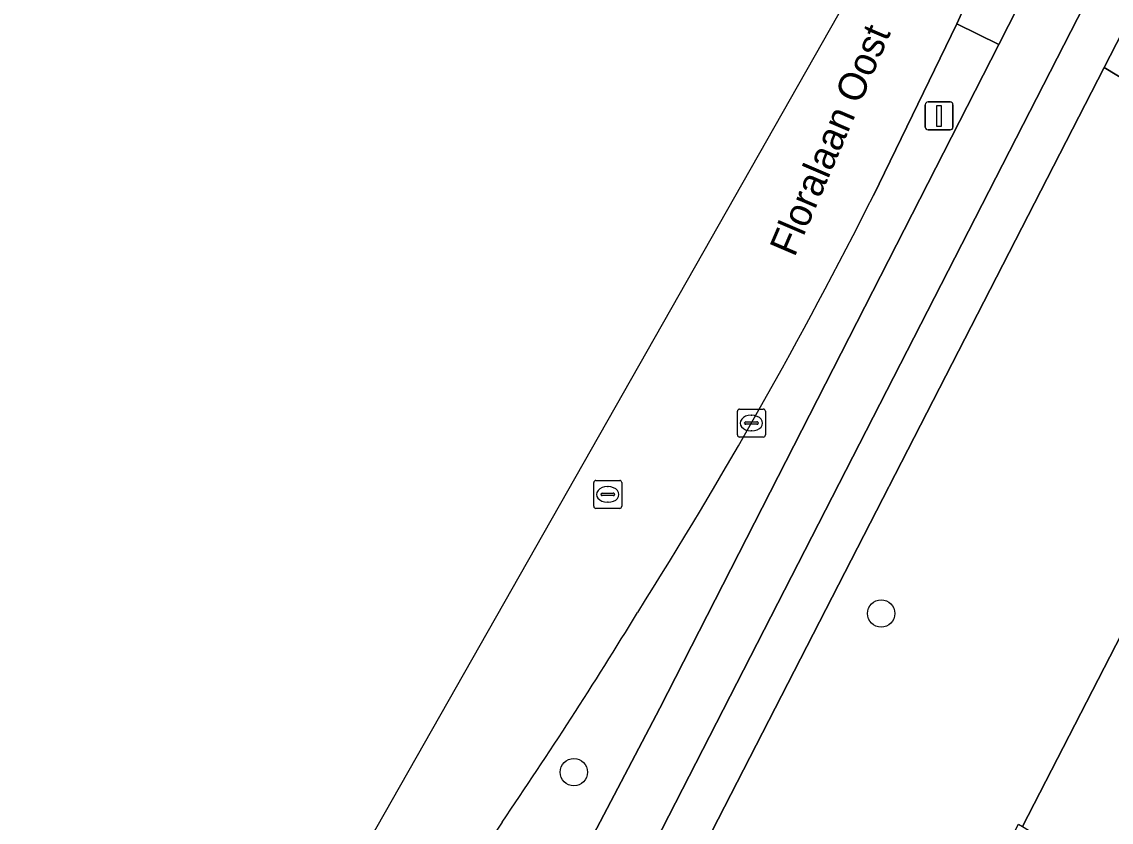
# Model space of a CAD drawing. Extents: x 162661 to 163484, y 380247 to 381230.
# Drawn here: x 163062.37 to 163101.35, y 380942.48 to 380971.11 of the extents above; entities that cross this region are included whole.
import ezdxf

# ---------------------------------------------------------------- set-up
doc = ezdxf.new("R2010")
doc.units = 0
for name, color, linetype in [('IMGEO_Berm_groen', 7, 'Continuous'), ('IMGEO_Berm_open', 7, 'Continuous'), ('IMGEO_Boom', 7, 'Continuous'), ('IMGEO_Erf', 7, 'Continuous'), ('IMGEO_Fietspad_open', 7, 'Continuous'), ('IMGEO_Gemengd_bos', 7, 'Continuous'), ('IMGEO_Kolk', 7, 'Continuous'), ('IMGEO_Lichtmast', 7, 'Continuous'), ('IMGEO_Openbare_ruimte_label', 7, 'Continuous'), ('IMGEO_Rijbaan_lokaal_gesloten', 7, 'Continuous'), ('IMGEO_Rioolput', 7, 'Continuous'), ('IMGEO_Voetpad_open', 7, 'Continuous')]:
    doc.layers.add(name, color=color, linetype=linetype)

msp = doc.modelspace()

# ---------------------------------------------------------------- linework, layer by layer
at = {"layer": 'IMGEO_Berm_groen'}
msp.add_lwpolyline([(163099.718, 380979.621), (163095.831, 380971.041), (163097.334, 380970.302), (163108.722, 380992.689), (163112.397, 380999.985), (163113.278, 381001.751)], dxfattribs=at)
at = {"layer": 'IMGEO_Berm_open'}
for points in [[(163097.334, 380970.302), (163095.831, 380971.041), (163092.842, 380964.895)], [(163079.556, 380942.482), (163078.602, 380941.045), (163081.312, 380939.161), (163085.202, 380946.557), (163097.334, 380970.302)]]:
    msp.add_lwpolyline(points, dxfattribs=at)
for centre, radius, start, end in [((162936.719, 381043.38), 174.741, 327.69234, 333.31081), ((162932.371, 381042.958), 178.21, 325.68046, 328.55401)]:
    msp.add_arc(centre, radius, start, end, dxfattribs=at)
at = {"layer": 'IMGEO_Boom'}
for centre in [(163093.122, 380949.947), (163082.127, 380944.274)]:
    msp.add_circle(centre, 0.489, dxfattribs=at)
at = {"layer": 'IMGEO_Erf'}
msp.add_lwpolyline([(163104.225, 380954.07), (163098.182, 380942.327), (163101.335, 380940.389), (163100.148, 380938.457), (163097.141, 380940.305), (163093.264, 380932.77), (163097.903, 380930.325), (163099.345, 380933.063), (163100.909, 380932.238), (163102.526, 380931.386), (163101.081, 380928.646), (163105.57, 380926.281)], dxfattribs=at)
at = {"layer": 'IMGEO_Fietspad_open'}
for points in [[(163113.278, 381001.751), (163112.397, 380999.985), (163108.722, 380992.689), (163097.334, 380970.302), (163085.202, 380946.557), (163081.312, 380939.161), (163078.602, 380941.045)], [(163078.572, 380932.781), (163078.201, 380932.005), (163077.707, 380931.721), (163077.359, 380931.919), (163078.839, 380929.669), (163080.32, 380932.543), (163082.573, 380934.938), (163082.967, 380936.912), (163083.252, 380937.877), (163083.627, 380938.938), (163084.062, 380939.851), (163114.537, 380999.295)]]:
    msp.add_lwpolyline(points, dxfattribs=at)
at = {"layer": 'IMGEO_Gemengd_bos'}
msp.add_lwpolyline([(163101.756, 380970.755), (163101.103, 380969.474), (163106.127, 380966.443), (163109.929, 380965.978), (163111.192, 380968.563), (163116.243, 380977.443), (163125.384, 380995.798), (163127.445, 380995.227), (163128.473, 381000), (163129.592, 381005.204), (163119.2, 381007.44), (163118.862, 381006.215), (163118.19, 381004.006), (163116.667, 381000)], close=True, dxfattribs=at)
for points in [[(163104.225, 380954.07), (163108.592, 380963.242), (163109.929, 380965.978), (163106.127, 380966.443), (163101.103, 380969.474), (163085.699, 380939.507), (163085.075, 380938.231)], [(163088.006, 380923.155), (163088.066, 380923.12), (163088.126, 380923.086), (163089.051, 380924.835), (163091.396, 380929.252), (163093.264, 380932.77), (163097.141, 380940.305), (163096.996, 380940.394), (163098.036, 380942.417), (163098.182, 380942.327), (163104.225, 380954.07)]]:
    msp.add_lwpolyline(points, dxfattribs=at)
at = {"layer": 'IMGEO_Kolk'}
for p, q in [((163088.053, 380957.259), (163088.905, 380957.259)), ((163087.978, 380956.333), (163087.978, 380957.185)), ((163088.466, 380957.039), (163088.491, 380957.039)), ((163088.979, 380957.185), (163088.979, 380956.333)), ((163088.237, 380956.753), (163088.237, 380956.765)), ((163088.675, 380956.716), (163088.277, 380956.716)), ((163088.28, 380956.802), (163088.678, 380956.802)), ((163088.489, 380956.479), (163088.464, 380956.479)), ((163088.721, 380956.765), (163088.721, 380956.753)), ((163088.905, 380956.259), (163088.053, 380956.259))]:
    msp.add_line(p, q, dxfattribs=at)
for points in [[(163088.053, 380957.259), (163088.905, 380957.259)], [(163087.978, 380956.333), (163087.978, 380957.185)], [(163088.979, 380957.185), (163088.979, 380956.333)], [(163088.905, 380956.259), (163088.053, 380956.259)]]:
    msp.add_lwpolyline(points, dxfattribs=at)
for centre, radius, start, end in [((163088.055, 380957.183), 0.0765, 91.552, 178.448), ((163088.055, 380957.183), 0.0765, 91.552, 178.448), ((163088.903, 380957.183), 0.0765, 1.552, 88.448), ((163088.903, 380957.183), 0.0765, 1.552, 88.448), ((163088.277, 380956.762), 0.0403, 85.8775, 175.7526), ((163088.274, 380956.752), 0.0366, 178.938, 274.7102), ((163088.678, 380956.759), 0.043, 264.8664, 352.4533), ((163088.682, 380956.764), 0.0386, 1.7309, 96.639), ((163088.055, 380956.335), 0.0765, 181.552, 268.448), ((163088.055, 380956.335), 0.0765, 181.552, 268.448), ((163088.903, 380956.335), 0.0765, 271.552, 358.448), ((163088.903, 380956.335), 0.0765, 271.552, 358.448)]:
    msp.add_arc(centre, radius, start, end, dxfattribs=at)
for centre, major_axis, ratio, start_param, end_param in [((163088.465, 380956.759), (-0.387, 0.002), 0.722429, 4.712389, 7.853982), ((163088.49, 380956.759), (-0.39, 0.002), 0.717154, 1.570796, 4.712389)]:
    msp.add_ellipse(centre, major_axis=major_axis, ratio=ratio, start_param=start_param, end_param=end_param, dxfattribs=at)
at = {"layer": 'IMGEO_Lichtmast'}
for p, q in [((163094.699, 380967.347), (163094.699, 380968.147)), ((163094.699, 380968.147), (163094.699, 380967.347)), ((163094.799, 380968.247), (163095.589, 380968.247)), ((163095.589, 380968.247), (163094.799, 380968.247)), ((163095.689, 380968.147), (163095.689, 380967.347)), ((163095.689, 380967.347), (163095.689, 380968.147)), ((163095.589, 380967.247), (163094.799, 380967.247)), ((163094.799, 380967.247), (163095.589, 380967.247))]:
    msp.add_line(p, q, dxfattribs=at)
msp.add_lwpolyline([(163095.119, 380968.122), (163095.269, 380968.122), (163095.269, 380967.372), (163095.119, 380967.372), (163095.119, 380968.122)], dxfattribs=at)
for centre, start, end in [((163094.799, 380968.147), 90, 180), ((163094.799, 380968.147), 90, 180), ((163095.589, 380968.147), 0, 90), ((163095.589, 380968.147), 360, 90), ((163094.799, 380967.347), 180, 270), ((163094.799, 380967.347), 180, 270), ((163095.589, 380967.347), 270, 0), ((163095.589, 380967.347), 270, 0)]:
    msp.add_arc(centre, 0.1, start, end, dxfattribs=at)
at = {"layer": 'IMGEO_Rijbaan_lokaal_gesloten'}
for points in [[(163106.974, 380999.872), (163107.445, 381001.581), (163120.284, 381048.133), (163142.304, 381127.974), (163143.035, 381130.883), (163143.543, 381132.838), (163140.547, 381133.584), (163139.069, 381133.952), (163135.379, 381116.471), (163114.525, 381043.88), (163099.48, 380989.07), (163092.997, 380973.876), (163069.643, 380932.768), (163062.369, 380926.22)], [(163092.842, 380964.895), (163095.831, 380971.041), (163099.718, 380979.621)]]:
    msp.add_lwpolyline(points, dxfattribs=at)
for centre, radius, start, end in [((162936.719, 381043.38), 174.741, 327.69234, 333.31081), ((162932.371, 381042.958), 178.21, 325.68046, 328.55401)]:
    msp.add_arc(centre, radius, start, end, dxfattribs=at)
at = {"layer": 'IMGEO_Rioolput'}
for p, q in [((163082.837, 380953.781), (163082.837, 380954.633)), ((163082.912, 380954.707), (163083.764, 380954.707)), ((163083.838, 380954.633), (163083.838, 380953.781)), ((163083.096, 380954.201), (163083.096, 380954.213)), ((163083.534, 380954.164), (163083.136, 380954.164)), ((163083.139, 380954.25), (163083.537, 380954.25)), ((163083.325, 380954.487), (163083.35, 380954.487)), ((163083.58, 380954.213), (163083.58, 380954.201)), ((163083.348, 380953.927), (163083.323, 380953.927)), ((163083.764, 380953.707), (163082.912, 380953.707))]:
    msp.add_line(p, q, dxfattribs=at)
for points in [[(163082.837, 380953.781), (163082.837, 380954.633)], [(163082.912, 380954.707), (163083.764, 380954.707)], [(163083.838, 380954.633), (163083.838, 380953.781)], [(163083.764, 380953.707), (163082.912, 380953.707)]]:
    msp.add_lwpolyline(points, dxfattribs=at)
for centre, radius, start, end in [((163082.914, 380954.631), 0.0765, 91.552, 178.448), ((163082.914, 380954.631), 0.0765, 91.552, 178.448), ((163083.762, 380954.631), 0.0765, 1.552, 88.448), ((163083.762, 380954.631), 0.0765, 1.552, 88.448), ((163083.136, 380954.21), 0.0403, 85.8775, 175.7526), ((163083.133, 380954.2), 0.0366, 178.938, 274.7102), ((163083.537, 380954.207), 0.043, 264.8664, 352.4533), ((163083.541, 380954.212), 0.0386, 1.7309, 96.639), ((163082.914, 380953.783), 0.0765, 181.552, 268.448), ((163082.914, 380953.783), 0.0765, 181.552, 268.448), ((163083.762, 380953.783), 0.0765, 271.552, 358.448), ((163083.762, 380953.783), 0.0765, 271.552, 358.448)]:
    msp.add_arc(centre, radius, start, end, dxfattribs=at)
for centre, major_axis, ratio, start_param, end_param in [((163083.324, 380954.207), (-0.387, 0.002), 0.722429, 4.712389, 7.853982), ((163083.349, 380954.207), (-0.39, 0.002), 0.717154, 1.570796, 4.712389)]:
    msp.add_ellipse(centre, major_axis=major_axis, ratio=ratio, start_param=start_param, end_param=end_param, dxfattribs=at)
at = {"layer": 'IMGEO_Voetpad_open'}
for points in [[(163117.677, 381007.997), (163117.342, 381006.837), (163116.385, 381003.634), (163114.897, 381000), (163114.537, 380999.295), (163084.062, 380939.851), (163083.627, 380938.938), (163083.252, 380937.877), (163082.967, 380936.912), (163082.573, 380934.938), (163084.365, 380935.219)], [(163085.075, 380938.231), (163085.699, 380939.507), (163101.103, 380969.474), (163101.756, 380970.755), (163116.667, 381000)]]:
    msp.add_lwpolyline(points, dxfattribs=at)

# ---------------------------------------------------------------- texts
at = {"layer": 'IMGEO_Openbare_ruimte_label'}
msp.add_text('Floralaan Oost', height=1, rotation=66.7939, dxfattribs=at).set_placement((163090.019, 380962.666))

doc.saveas('drawing.dxf')
